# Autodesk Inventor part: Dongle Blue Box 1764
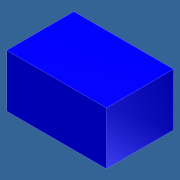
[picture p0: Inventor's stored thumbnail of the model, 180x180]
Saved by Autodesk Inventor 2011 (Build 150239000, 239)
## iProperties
Created: 2010-01
Part Number: Dongle Blue Box 1764
Document SubType Name: Modeling
Designer: jgehrig
Density: 1 g/cm^3
Author: jgehrig
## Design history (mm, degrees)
sketch "Sketch1"
  geometry: L1 (-17.846, -0.772)-(-4.638, -0.772); L2 (-4.638, -0.772)-(-4.638, -7.757); L3 (-4.638, -7.757)-(-17.846, -7.757); L4 (-17.846, -7.757)-(-17.846, -0.772); 1 further point
  constraints: 8 end point, 2 parallel, 1 horizontal, 1 perpendicular
  dimensions: "d0" = 6.985 distance of L3.end L1.start; "d1" = 13.208 distance of L2.end L3.end
extrude "Extrusion1" new body sketch "Sketch1" distance "d2" = 8.89; taper "d3" = 0 deg
body "Solid1"
